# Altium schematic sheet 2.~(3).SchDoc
size 420 x 297 mm
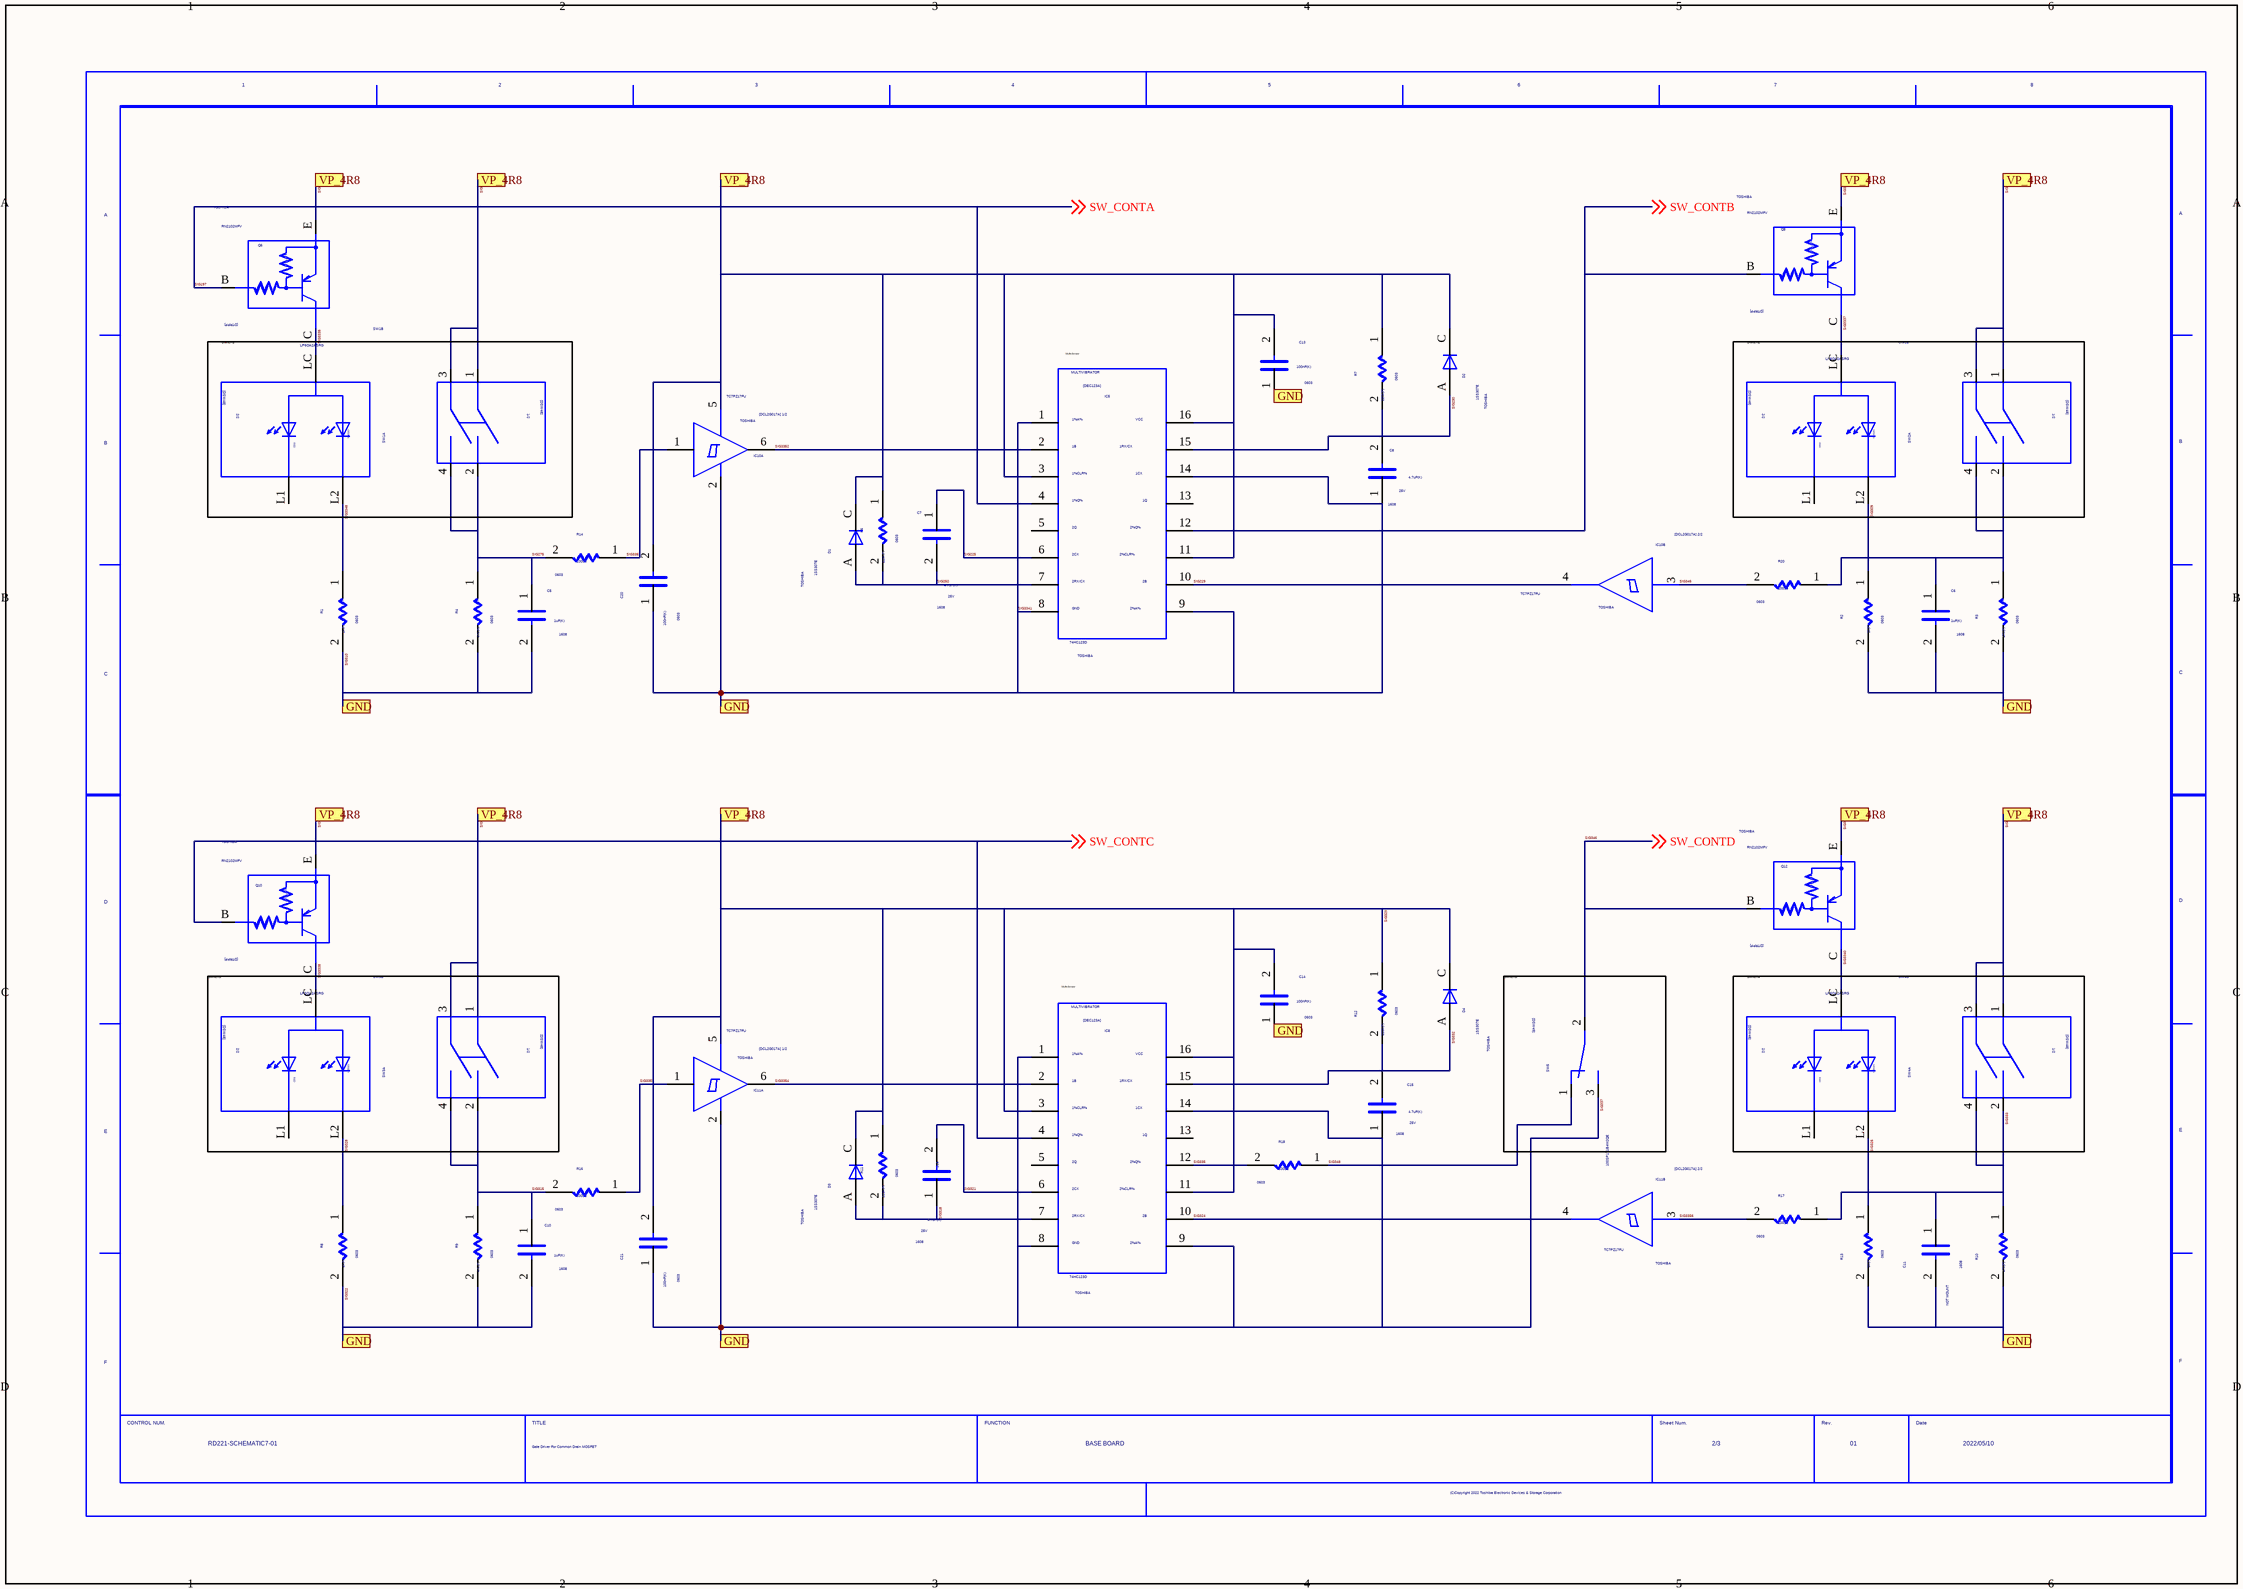
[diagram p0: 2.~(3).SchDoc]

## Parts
C5  SIZECODESMD: 1608  VAL1: 1uF(K)  (hidden comment: DC)
C6  SIZECODESMD: 1608  VAL1: 1uF(K)  (hidden comment: DC)
C7  SIZECODESMD: 1608  VAL2: 25V  VAL1: 4.7uF(K)  (hidden comment: DC)
C8  SIZECODESMD: 1608  VAL2: 25V  VAL1: 4.7uF(K)  (hidden comment: DC)
C10  SIZECODESMD: 1608  VAL1: 1uF(K)  (hidden comment: DC)
C11  NOTMOUNT: NOT MOUNT  SIZECODESMD: 1608  (hidden comment: DC)
C13  SIZECODESMD: 0603  VAL1: 100nF(K)  (hidden comment: DC)
C14  SIZECODESMD: 0603  VAL1: 100nF(K)  (hidden comment: DC)
C15  SIZECODESMD: 1608  VAL2: 25V  VAL1: 4.7uF(K)  (hidden comment: DC)
C16  SIZECODESMD: 1608  VAL2: 25V  VAL1: 4.7uF(K)  (hidden comment: DC)
C20  SIZECODESMD: 0603  VAL1: 100nF(K)  (hidden comment: DC)
C21  SIZECODESMD: 0603  VAL1: 100nF(K)  (hidden comment: DC)
D1  USERCOMPTEXT3: TOSHIBA  VAL1: 1SS307E  (hidden comment: DD)
D2  USERCOMPTEXT3: TOSHIBA  VAL1: 1SS307E  (hidden comment: DD)
D3  USERCOMPTEXT3: TOSHIBA  VAL1: 1SS307E  (hidden comment: DD)
D4  USERCOMPTEXT3: TOSHIBA  VAL1: 1SS307E  (hidden comment: DD)
IC5  USERCOMPTEXT3: TOSHIBA  VAL1: 74HC123D  (hidden comment: DEC123A)
IC8  USERCOMPTEXT3: TOSHIBA  VAL1: 74HC123D  (hidden comment: DEC123A)
IC10  USERCOMPTEXT3: TOSHIBA  VAL3: TC7PZ17FU  (hidden comment: DCL2G017A_1)  (parts A,B of 2)
IC11  USERCOMPTEXT3: TOSHIBA  VAL3: TC7PZ17FU  (hidden comment: DCL2G017A_1)  (parts A,B of 2)
Q6  USERCOMPTEXT3: TOSHIBA  VAL1: RN2102MFV  (hidden comment: DTRPF)
Q8  USERCOMPTEXT3: TOSHIBA  VAL1: RN2102MFV  (hidden comment: DTRPF)
Q10  USERCOMPTEXT3: TOSHIBA  VAL1: RN2102MFV  (hidden comment: DTRPF)
Q12  USERCOMPTEXT3: TOSHIBA  VAL1: RN2102MFV  (hidden comment: DTRPF)
R1  SIZECODESMD: 0603  VAL1: 1k(F)  (hidden comment: DR)
R2  SIZECODESMD: 0603  VAL1: 1k(F)  (hidden comment: DR)
R3  SIZECODESMD: 0603  VAL1: 47k(F)  (hidden comment: DR)
R4  SIZECODESMD: 0603  VAL1: 47k(F)  (hidden comment: DR)
R6  SIZECODESMD: 0603  VAL1: 220k(F)  (hidden comment: DR)
R7  SIZECODESMD: 0603  VAL1: 220k(F)  (hidden comment: DR)
R8  SIZECODESMD: 0603  VAL1: 1k(F)  (hidden comment: DR)
R9  SIZECODESMD: 0603  VAL1: 47k(F)  (hidden comment: DR)
R10  SIZECODESMD: 0603  VAL1: 47k(F)  (hidden comment: DR)
R11  SIZECODESMD: 0603  VAL1: 220k(F)  (hidden comment: DR)
R12  SIZECODESMD: 0603  VAL1: 220k(F)  (hidden comment: DR)
R13  SIZECODESMD: 0603  VAL1: 1k(F)  (hidden comment: DR)
R14  SIZECODESMD: 0603  VAL1: 100(J)  (hidden comment: DR)
R16  SIZECODESMD: 0603  VAL1: 100(J)  (hidden comment: DR)
R17  SIZECODESMD: 0603  VAL1: 100(J)  (hidden comment: DR)
R18  SIZECODESMD: 0603  VAL1: 100(J)  (hidden comment: DR)
R20  SIZECODESMD: 0603  VAL1: 100(J)  (hidden comment: DR)
SW1  DSW48_1  (value not drawn)  (parts A,B of 2)
SW2  DSW48_1  (value not drawn)  (parts A,B of 2)
SW3  DSW48_1  (value not drawn)  (parts A,B of 2)
SW4  DSW48_1  (value not drawn)  (parts A,B of 2)
SW5  VAL3: 100SP1T1B4M2QE  (hidden comment: DSW49)
U?  DATE: 2022/05/10  DRAWINGNUMBER: RD221-SCHEMATIC7-01  REVISION: 01  FUNCTION: BASE BOARD  SHEETNUMBER: 2/3  TITLE: Gate Driver For Common Drain MOSFET  (hidden comment: WAKU_DEF100)

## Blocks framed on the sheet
Switch1: SW1
Switch2: SW2
Switch3: SW3
Switch5: SW5
Switch4: SW4

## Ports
GND, VP_4R8

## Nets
SIG197: IC5.4 Q6.B ; off-sheet SW_CONTA  [also labelled SW_CONTA]
SIG225: C7.1 IC5.6
SIG229: IC5.10 IC10.4
SIG230: C8.2 D2.A IC5.15 R7.2
SIG250: C7.2 D1.A IC5.7 R6.2
SIG275: C5.1 R4.1 R14.2 SW1.2 SW1.4
SIG276: C13.2 C14.2 C20.2 C21.2 D1.C D2.C D3.C D4.C IC5.3 IC5.11 IC5.16 IC8.3 IC8.11 IC8.16 IC10.5 IC11.5 Q6.E Q8.E Q10.E Q12.E R6.1 R7.1 R11.1 R12.1 SW1.1 SW1.3 SW2.1 SW2.3 SW3.1 SW3.3 SW4.1 SW4.3 ; port VP_4R8  [also labelled SIG303, SIG308, SIG317, SIG325, SIG327, SIG329, SIG3336, SIG3339]
SIG309: R2.1 SW2.L2
SIG310: C5.2 C6.2 C8.1 C10.2 C11.2 C13.1 C14.1 C15.1 C20.1 C21.1 IC5.1 IC5.8 IC5.9 IC5.14 IC8.1 IC8.8 IC8.9 IC8.14 IC10.2 IC11.2 R1.2 R2.2 R3.2 R4.2 R8.2 R9.2 R10.2 R13.2 SW5.3 ; port GND  [also labelled SIG312, SIG322, SIG3341, SIG336, SIG337]
SIG313: C6.1 R3.1 R20.1 SW2.2 SW2.4
SIG315: C10.1 R9.1 R16.2 SW3.2 SW3.4
SIG318: C16.1 D3.A IC8.7 R11.2
SIG321: C16.2 IC8.6
SIG324: IC8.10 IC11.4
SIG326: R13.1 SW4.L2
SIG328: R8.1 SW3.L2
SIG332: C15.2 D4.A IC8.15 R12.2
SIG333: C11.1 R10.1 R17.1 SW4.2 SW4.4
SIG335: IC8.12 R18.2
SIG345: IC10.3 R20.2
SIG346: Q12.B SW5.2 ; off-sheet SW_CONTD  [also labelled SW_CONTD]
SIG348: R18.1 SW5.1
SIG3335: Q6.C SW1.LC
SIG3337: Q8.C SW2.LC
SIG3338: Q10.C SW3.LC
SIG3340: Q12.C SW4.LC
SIG3348: R1.1 SW1.L2
SIG3352: IC5.2 IC10.6
SIG3353: IC10.1 R14.1
SIG3354: IC8.2 IC11.6
SIG3355: IC11.1 R16.1
SIG3356: IC11.3 R17.2
SW_CONTB: IC5.12 Q8.B ; off-sheet SW_CONTB
SW_CONTC: IC8.4 Q10.B ; off-sheet SW_CONTC

Not connected (* = marked no-connect by the designer): IC5 5 13; IC8 5 13; SW1 L1; SW2 L1; SW3 L1; SW4 L1

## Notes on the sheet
- Multivibrator

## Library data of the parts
C5 C6 C10 = DC: OUMEPARTTYPE: C; OriginalSymbolOrigin: (2540,7620); MAXGCOUNT: 1; COMPONENTNAME: DP0000149011_package; COMP: DP0000149011; VAL3: GMK107BJ105KA-T; VAL2: 35V
C7 C8 C15 C16 = DC: OUMEPARTTYPE: C; OriginalSymbolOrigin: (2540,7620); COMPONENTNAME: DP0000017116_package; MAXGCOUNT: 1; COMP: DP0000017116; VAL3: GRM188R61E475KE15D
C11 = DC: OUMEPARTTYPE: C; OriginalSymbolOrigin: (2540,7620); MAXGCOUNT: 1; COMPONENTNAME: DP0000149011_package; COMP: DP0000149011; VAL3: GMK107BJ105KA-T; VAL2: 35V; VAL1: 1uF(K)
C13 C14 C20 C21 = DC: OUMEPARTTYPE: C; OriginalSymbolOrigin: (2540,7620); MAXGCOUNT: 1; COMPONENTNAME: DP0000015406_package; COMP: DP0000015406; VAL3: GRM033R61C104KE14D; VAL2: 16V
D1-D4 = DD: OUMEPARTTYPE: D; SAVEAREA0: -225,-91,12804,7836; SAVECOUNT: 3; TIME: 14:49:55; UPDATEUSER: 19870035; UPDATETIME: 14:20:16; OriginalSymbolOrigin: (5080,5080); COMPONENTNAME: DP0005002000_package; MAXGCOUNT: 1; COMP: DP0005002000
IC5 IC8 = DEC123A: OUMEPARTTYPE: IC; SAVEAREA0: -51950,-1012,82634,54279; SAVECOUNT: 6; TIME: 14:53:14; UPDATEUSER: w90028dm; UPDATETIME: 14:48:13; OriginalSymbolOrigin: (5080,50800); COMPONENTNAME: DP0010568000_package; MAXGCOUNT: 1; COMP: DP0010568000
IC10 IC11 = DCL2G017A_1: OUMEPARTTYPE: IC; TIME: 14:48:25; UPDATEUSER: w90028dm; UPDATETIME: 11:00:47; SAVECOUNT: 12; SAVEAREA0: -27668,-19920,47920,35415; OriginalSymbolOrigin: (0,12700); CaptureCellPackProp: DCL2G017A_1A; COMPONENTNAME: DCL2G017A_pinAssign_DCL2G017A_1_function; MAXGCOUNT: 1; COMP: DP0010608000; FUNCN: DCL2G017A_1_function
Q6 Q8 Q10 Q12 = DTRPF: PARTS: 1; OUMEPARTTYPE: Q; HETERO: RN4905_1,RN4905_2; FUNCTION: PNP&NPN_PCT; LEVEL: STD; PKG_TYPE: 2-2J1A; DEVICE: RN4905; SAVECOUNT: 12; SAVEAREA0: -44788,-13627,70567,33764; DEVICENAME: RN2104; TIME: 19:37:19; UPDATEUSER: w90028dm; UPDATETIME: 15:25:57; OriginalSymbolOrigin: (2540,20320); COMPONENTNAME: DP0010570000_package; COMP: DP0010570000
R1 R2 R8 R13 = DR: OUMEPARTTYPE: R; OriginalSymbolOrigin: (5080,5080); MAXGCOUNT: 1; COMPONENTNAME: DP0000152048; VAL3: ERJ1GNF1001C; VAL2: 50mW
R3 R4 R9 R10 = DR: OUMEPARTTYPE: R; OriginalSymbolOrigin: (5080,5080); MAXGCOUNT: 1; COMPONENTNAME: DP0000152088; VAL3: ERJ1GNF4702C; VAL2: 50mW
R6 R11 = DR: OUMEPARTTYPE: R; OriginalSymbolOrigin: (5080,5080); MAXGCOUNT: 1; COMPONENTNAME: DP0000152104; VAL3: ERJ1GNF2203C; VAL2: 50mW
R7 R12 = DR: OUMEPARTTYPE: R; OriginalSymbolOrigin: (5080,5080); MAXGCOUNT: 1; COMPONENTNAME: DP0000155128; VAL3: RK73B1HTTC224J; VAL2: 50mW
R14 R16-R18 R20 = DR: OUMEPARTTYPE: R; OriginalSymbolOrigin: (5080,5080); MAXGCOUNT: 1; COMPONENTNAME: DP0000155000_package; COMP: DP0000155000; VAL3: RK73B1HTTC101J; VAL2: 50mW
SW1-SW4 = DSW48_1: PARTS: 1; OUMEPARTTYPE: S; SAVECOUNT: 17; SAVEAREA0: -14290,-6784,35003,29302; TIME: 19:37:19; UPDATEUSER: w90028dm; UPDATETIME: 08:14:33; OriginalSymbolOrigin: (2540,20320); HETERO: RN4905_1,RN4905_2; FUNCTION: PNP&NPN_PCT; LEVEL: STD; P/D_NUM: TOSHIBA; PKG_TYPE: 2-2J1A; DEVICE: RN4905; DEVICENAME: RN2104; CLASS: DISCRETE; CaptureCellPackProp: DSW48_1A; RATEDCURRENT: 12m; RATEDVOLTAGE: 12; COMPONENTNAME: DSW48_pinAssign_DSW48_2_function; OUMEMAKER: ZZZ ＊＊＊暫定＊＊＊; FNLEADFREETHET1GT2GMCTH1: N_N_N; OUMECLASSIFICATION: プッシュボタン／タクトスイッチ; MOUNTINGFORM: 挿入実装; COMP: DP0010571000; FUNCN: DSW48_2_function; ADSCNVFLAG: ON; OUMEMAKERKATAMEI: LP6OA2ASRG; NUMBEROFPOSITIO: 2POS
SW5 = DSW49: OUMEPARTTYPE: S; SAVEAREA0: -42205,-15236,59041,26359; TIME: 14:45:03; UPDATEUSER: w90028dm; UPDATETIME: 17:53:32; SAVECOUNT: 4; OriginalSymbolOrigin: (2540,10160); COMPONENTNAME: DP0010575000_package; MAXGCOUNT: 1; COMP: DP0010575000
U? = WAKU_DEF100: PLOTTIME: HH:MM; SAVEAREA0: 148187,-66180,486823,89919; TIME: 14:30:25; UPDATEUSER: t5459927; UPDATETIME: 16:52:10; SAVECOUNT: 6; OriginalSymbolOrigin: (10160,284480)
